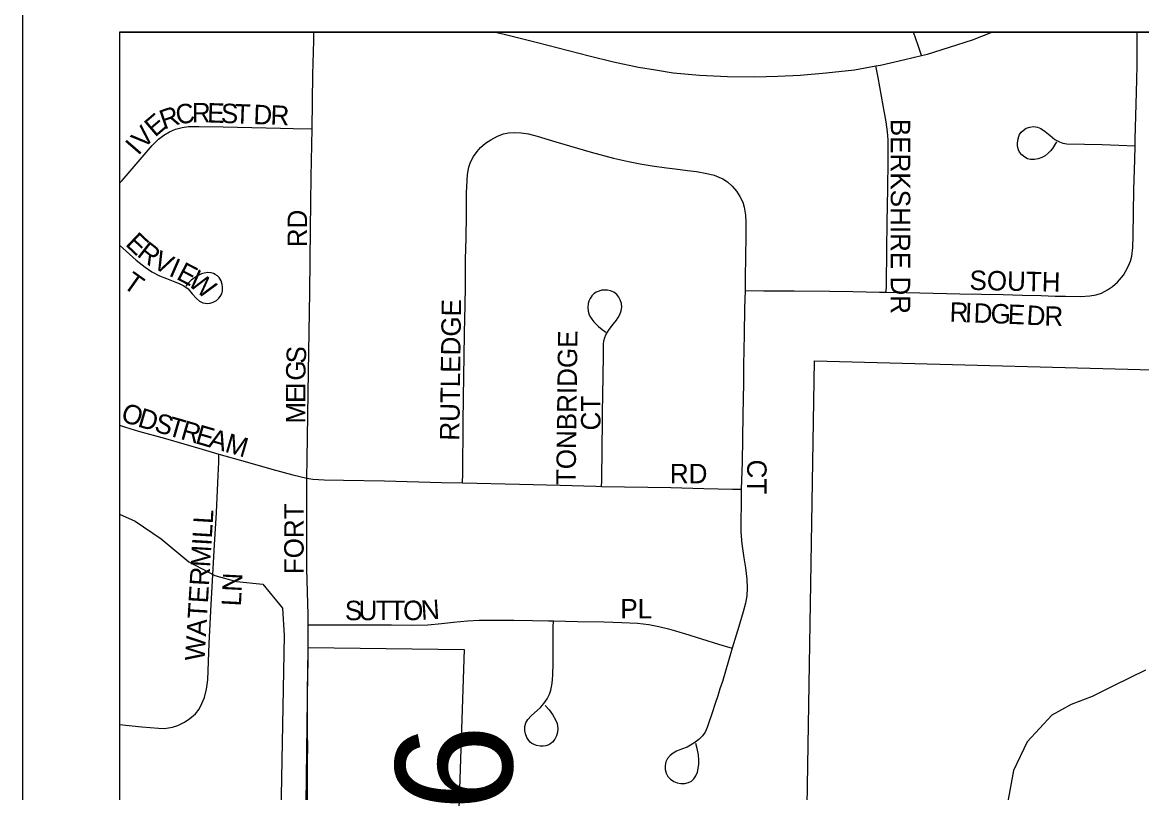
# Model space of a CAD drawing. Extents: x -5.6 to 34, y 0 to 22.
# Drawn here: x 2 to 3.152, y 20.118 to 20.91 of the extents above; entities that cross this region are included whole.
import ezdxf

# ---------------------------------------------------------------- set-up
doc = ezdxf.new("R2010")
doc.units = 0
for name, color, linetype in [('GM_X_City_Street', 7, 'Continuous'), ('GM_X_City_Street_Text', 7, 'Continuous'), ('GM_X_Corporation', 7, 'Continuous'), ('GM_X_Minor_River', 7, 'Continuous'), ('GM_X_State_Route', 7, 'Continuous'), ('GM_X_Township', 7, 'Continuous'), ('GM_X_Township_Road', 7, 'Continuous'), ('GM_X_Township_Road_Text', 7, 'Continuous'), ('SH_Data', 7, 'Continuous')]:
    doc.layers.add(name, color=color, linetype=linetype)

msp = doc.modelspace()

# ---------------------------------------------------------------- linework, layer by layer
at = {"layer": 'GM_X_City_Street'}
for points in [[(2.2982, 20.8008), (2.299, 20.8567), (2.2997, 20.8915), (2.2999, 20.9)], [(2.9252, 20.8761), (2.9215, 20.8865), (2.9168, 20.9)], [(3.1448, 20.7831), (3.1449, 20.7902), (3.1462, 20.838), (3.147, 20.8656), (3.147, 20.8814), (3.147, 20.8916), (3.147, 20.9)], [(2.8888, 20.6327), (2.8889, 20.64), (2.8895, 20.6768), (2.8897, 20.7042), (2.8903, 20.7393), (2.8908, 20.7673), (2.8908, 20.7825), (2.8908, 20.7895), (2.8902, 20.7976), (2.8886, 20.808), (2.8857, 20.8245), (2.8804, 20.8534), (2.8782, 20.8655)], [(2.1, 20.7447), (2.1025, 20.7477), (2.1334, 20.7835), (2.1402, 20.79), (2.1455, 20.7942), (2.1514, 20.7977), (2.1577, 20.8003), (2.1643, 20.802), (2.171, 20.8029), (2.1817, 20.8032), (2.2066, 20.8026), (2.2656, 20.8012), (2.2787, 20.8011), (2.2982, 20.8008)], [(2.2928, 20.4415), (2.2931, 20.4614), (2.2944, 20.5508), (2.2958, 20.6327), (2.2963, 20.6977), (2.2971, 20.7512), (2.2982, 20.8008)], [(2.4529, 20.4366), (2.453, 20.4458), (2.4535, 20.4988), (2.4538, 20.5243), (2.4544, 20.5675), (2.4548, 20.5893), (2.4552, 20.6067), (2.4554, 20.6172), (2.4558, 20.6409), (2.456, 20.6513), (2.456, 20.6665), (2.4565, 20.6881), (2.4568, 20.7127), (2.4568, 20.7301), (2.4571, 20.7357), (2.4572, 20.7408), (2.4576, 20.7478), (2.4581, 20.7537), (2.4595, 20.7614), (2.4612, 20.7664), (2.4642, 20.7722), (2.468, 20.7775), (2.4715, 20.7814), (2.4765, 20.7858), (2.4819, 20.7894), (2.4888, 20.7931), (2.495, 20.7955), (2.5001, 20.7966), (2.5067, 20.797), (2.5132, 20.7966), (2.5207, 20.7955), (2.5297, 20.793), (2.5488, 20.7873), (2.5852, 20.7767), (2.6082, 20.7706), (2.6236, 20.7671), (2.6357, 20.7647), (2.648, 20.7626), (2.6627, 20.7606), (2.6716, 20.7595), (2.6843, 20.7579), (2.6935, 20.7568), (2.7041, 20.7549), (2.7117, 20.7529), (2.7167, 20.751), (2.7207, 20.7493), (2.7254, 20.7461), (2.7304, 20.7416), (2.7347, 20.7366), (2.7383, 20.7311), (2.7411, 20.7252), (2.7425, 20.7201), (2.7439, 20.712), (2.7442, 20.7047), (2.7445, 20.6902), (2.7437, 20.6478), (2.7437, 20.6344)], [(3.0639, 20.7872), (3.0597, 20.7805), (3.0577, 20.7779), (3.0553, 20.7755), (3.0523, 20.773), (3.0488, 20.7711), (3.0451, 20.7698), (3.0413, 20.7691), (3.0373, 20.7691), (3.034, 20.7699), (3.0313, 20.7714), (3.0283, 20.7738), (3.0259, 20.7768), (3.0248, 20.7791), (3.0241, 20.7815), (3.0239, 20.7831), (3.0238, 20.7852), (3.0241, 20.789), (3.0251, 20.7928), (3.026, 20.7949), (3.0275, 20.7972), (3.0295, 20.7991), (3.0328, 20.8013), (3.0365, 20.8025), (3.0404, 20.8029), (3.0443, 20.8023), (3.0479, 20.8009), (3.0523, 20.798), (3.0573, 20.7938), (3.0624, 20.7897), (3.0669, 20.7872), (3.0706, 20.786), (3.0745, 20.7853), (3.1111, 20.7844), (3.1281, 20.7838), (3.1448, 20.7831)], [(2.8888, 20.6327), (2.9095, 20.6323), (2.9646, 20.6309), (3.0092, 20.6302), (3.0291, 20.6297), (3.0482, 20.6292), (3.0625, 20.6286), (3.0733, 20.6287), (3.0891, 20.6282), (3.0982, 20.6289), (3.1047, 20.6301), (3.1101, 20.6317), (3.1166, 20.6351), (3.1216, 20.6385), (3.1267, 20.6429), (3.1328, 20.6502), (3.135, 20.654), (3.1382, 20.6597), (3.1402, 20.6646), (3.1415, 20.6696), (3.1425, 20.6788), (3.1428, 20.6906), (3.1437, 20.7378), (3.1446, 20.7692), (3.1448, 20.7831)], [(2.1, 20.6809), (2.117, 20.6656), (2.1262, 20.6585), (2.1331, 20.6537), (2.1411, 20.6496), (2.1483, 20.6467), (2.155, 20.6441), (2.1612, 20.6418), (2.1662, 20.6392), (2.1704, 20.636), (2.1748, 20.6311), (2.1791, 20.6262), (2.1821, 20.6236), (2.1835, 20.6227), (2.1856, 20.6219), (2.1881, 20.6213), (2.1902, 20.6212), (2.1933, 20.6214), (2.1963, 20.6224), (2.1996, 20.6243), (2.202, 20.6264), (2.2035, 20.6281), (2.2051, 20.631), (2.2058, 20.634), (2.206, 20.638), (2.2056, 20.6406), (2.2045, 20.6444), (2.2024, 20.6477), (2.2006, 20.6496), (2.1984, 20.651), (2.1965, 20.6519), (2.1941, 20.6526), (2.1908, 20.6528), (2.1869, 20.6522), (2.1844, 20.6516), (2.1817, 20.6503), (2.1791, 20.6489), (2.1761, 20.6469), (2.1738, 20.6449), (2.1714, 20.6427), (2.1683, 20.6389)], [(2.596, 20.433), (2.5961, 20.4387), (2.5965, 20.4739), (2.5968, 20.4976), (2.5969, 20.5094), (2.5972, 20.5265), (2.5978, 20.5673), (2.598, 20.5791), (2.5984, 20.5826), (2.5992, 20.586), (2.6004, 20.589), (2.6036, 20.5943), (2.6081, 20.6), (2.6111, 20.6039), (2.6131, 20.6067), (2.6148, 20.6098), (2.6162, 20.6135), (2.6166, 20.6173), (2.6164, 20.6212), (2.6151, 20.6249), (2.6136, 20.6276), (2.6115, 20.6302), (2.6085, 20.6326), (2.6051, 20.6342), (2.602, 20.6349), (2.599, 20.6349), (2.596, 20.6347), (2.5933, 20.6339), (2.5905, 20.6326), (2.5881, 20.6309), (2.5859, 20.6289), (2.5842, 20.6263), (2.5828, 20.6236), (2.5821, 20.6209), (2.5816, 20.617), (2.5821, 20.6132), (2.5833, 20.6094), (2.5845, 20.6069), (2.5858, 20.6049), (2.588, 20.6021), (2.5902, 20.5999), (2.5929, 20.5974), (2.5966, 20.5943), (2.6002, 20.5916)], [(2.7437, 20.6344), (2.7431, 20.6161), (2.7425, 20.5892), (2.742, 20.5577), (2.742, 20.5393), (2.7412, 20.5066), (2.7405, 20.458), (2.7396, 20.4301)], [(2.7437, 20.6344), (2.7627, 20.6341), (2.777, 20.6341), (2.7941, 20.634), (2.8308, 20.6336), (2.8544, 20.6333), (2.882, 20.6328), (2.8888, 20.6327)], [(2.1, 20.4961), (2.1062, 20.4939), (2.1196, 20.4898), (2.1473, 20.4821), (2.1851, 20.4712), (2.2022, 20.4663)], [(2.1, 20.1883), (2.1228, 20.1857), (2.14, 20.1844), (2.1463, 20.1842), (2.1545, 20.1853), (2.16, 20.1872), (2.1667, 20.1905), (2.1723, 20.1942), (2.1782, 20.199), (2.1819, 20.2039), (2.1848, 20.2098), (2.1874, 20.2161), (2.1896, 20.2246), (2.1908, 20.2342), (2.1922, 20.2713), (2.1944, 20.3117), (2.1977, 20.3728), (2.1996, 20.4061), (2.2014, 20.4443), (2.2021, 20.458), (2.2022, 20.4663)], [(2.2022, 20.4663), (2.2291, 20.4586), (2.2567, 20.4508), (2.2783, 20.4448), (2.2928, 20.4415)], [(2.294, 20.2908), (2.294, 20.301), (2.2928, 20.3482), (2.2926, 20.3907), (2.2928, 20.4415)], [(2.2928, 20.4415), (2.2988, 20.4406), (2.3104, 20.4398), (2.3304, 20.4394), (2.3724, 20.4386), (2.4313, 20.4371), (2.4529, 20.4366)], [(2.4529, 20.4366), (2.5113, 20.4352), (2.5532, 20.4342), (2.5899, 20.4331), (2.596, 20.433)], [(2.596, 20.433), (2.6672, 20.4317), (2.7012, 20.4309), (2.7307, 20.4303), (2.7396, 20.4301)], [(2.7396, 20.4301), (2.7395, 20.4265), (2.7392, 20.3858), (2.7401, 20.374), (2.7422, 20.3597), (2.7439, 20.3494), (2.7452, 20.3377), (2.7456, 20.3285), (2.7452, 20.3206), (2.7441, 20.3128), (2.7416, 20.304), (2.7372, 20.2889), (2.7304, 20.2665)], [(2.294, 20.2908), (2.3042, 20.2908), (2.3298, 20.2908), (2.3799, 20.2905), (2.4017, 20.2903), (2.417, 20.2908), (2.4313, 20.2919), (2.4437, 20.2933), (2.458, 20.2946), (2.4698, 20.2954), (2.487, 20.2954), (2.5056, 20.2954), (2.5247, 20.2952), (2.5412, 20.2947), (2.5463, 20.2946)], [(2.294, 20.2674), (2.294, 20.2777), (2.294, 20.2908)], [(2.538, 20.2077), (2.542, 20.2031), (2.5455, 20.1985), (2.5486, 20.1931), (2.5501, 20.1891), (2.5508, 20.1842), (2.5506, 20.1803), (2.5497, 20.1765), (2.5478, 20.173), (2.5453, 20.17), (2.5438, 20.1687), (2.5416, 20.1673), (2.5385, 20.1662), (2.5359, 20.1658), (2.5327, 20.1658), (2.5291, 20.1665), (2.5265, 20.1675), (2.5243, 20.1686), (2.5226, 20.17), (2.521, 20.1716), (2.519, 20.1748), (2.5175, 20.1784), (2.517, 20.182), (2.517, 20.186), (2.518, 20.1898), (2.52, 20.1932), (2.5234, 20.1972), (2.5331, 20.2057), (2.5366, 20.2097), (2.5401, 20.2147), (2.5425, 20.2195), (2.5438, 20.2234), (2.5449, 20.2286), (2.5454, 20.2336), (2.5459, 20.24), (2.5461, 20.2504), (2.5461, 20.2599), (2.5461, 20.2708), (2.5461, 20.2814), (2.5461, 20.2883), (2.5463, 20.2946)], [(2.5463, 20.2946), (2.571, 20.2941), (2.5983, 20.2936), (2.6166, 20.2931), (2.6327, 20.2923), (2.6446, 20.291), (2.6547, 20.2891), (2.6647, 20.2865), (2.6719, 20.2845), (2.6765, 20.283), (2.6811, 20.2816), (2.7162, 20.2709), (2.7304, 20.2665)], [(2.7304, 20.2665), (2.7265, 20.2538), (2.7202, 20.2323), (2.7176, 20.2247), (2.7154, 20.2178), (2.7127, 20.2097), (2.7096, 20.2001), (2.7059, 20.1892), (2.7046, 20.1851), (2.7025, 20.1804), (2.6997, 20.1764), (2.696, 20.1727), (2.6908, 20.1688), (2.6839, 20.1649), (2.6782, 20.1627), (2.6729, 20.1607), (2.6694, 20.1588), (2.6664, 20.1563), (2.6638, 20.1533), (2.6621, 20.1498), (2.6613, 20.1459), (2.6613, 20.142), (2.6623, 20.1382), (2.6642, 20.1348), (2.6668, 20.1319), (2.6701, 20.1297), (2.6738, 20.1282), (2.6776, 20.1275), (2.6816, 20.1276), (2.6854, 20.1286), (2.6884, 20.1299), (2.6907, 20.1322), (2.693, 20.1354), (2.6945, 20.1391), (2.6954, 20.1429), (2.696, 20.1475), (2.6961, 20.1516), (2.6956, 20.157), (2.6942, 20.1635), (2.6929, 20.1685)]]:
    msp.add_lwpolyline(points, dxfattribs=at)
at = {"layer": 'GM_X_Corporation'}
for points in [[(3.2277, 20.9), (2.1, 20.9), (2.1, 18.226), (2.1688, 18.2231), (2.1708, 18.2767), (2.3867, 18.2751), (2.1, 17.7957), (2.1, 16.1715), (2.1566, 16.1698), (2.1557, 16.0644), (2.1, 16.0648), (2.1, 15.8951), (2.1803, 15.8911), (2.1794, 15.8126), (2.1472, 15.8117), (2.1446, 15.7502), (2.1, 15.7518), (2.1, 15.0823), (2.1322, 15.0813), (2.127, 14.9352), (2.1, 14.9372), (2.1, 14.8511)], [(3.1536, 18.9777), (2.7717, 18.9999), (3.0577, 19.4693), (3.04, 19.5098), (2.9528, 19.5113), (2.9527, 19.7435), (2.6819, 19.7478), (2.6801, 19.7916), (2.6052, 19.7912), (2.6079, 19.8804), (2.7143, 19.8786), (2.8037, 19.8757), (2.8151, 20.562), (3.2274, 20.5511)]]:
    msp.add_lwpolyline(points, dxfattribs=at)
msp.add_lwpolyline([(2.294, 20.2674), (2.4545, 20.2654), (2.442, 19.8863), (2.4544, 19.8859), (2.4479, 19.5945), (2.2856, 19.6003)], close=True, dxfattribs=at)
at = {"layer": 'GM_X_Minor_River'}
for points in [[(2.1, 20.4045), (2.116, 20.3974), (2.1428, 20.3792), (2.1711, 20.3554), (2.198, 20.3413), (2.2202, 20.3353), (2.2473, 20.3324), (2.2676, 20.3079), (2.2695, 20.2798)], [(2.2695, 20.2798), (2.266, 20.0963), (2.2602, 19.871), (2.257, 19.6153), (2.2485, 19.2874), (2.2423, 19.0438), (2.2144, 19.0427), (2.1857, 19.0432), (2.1665, 19.0444), (2.1529, 19.043), (2.1385, 19.0409), (2.1192, 19.0316), (2.1086, 19.0206), (2.1004, 19.0079), (2.1, 19.0071)], [(3.1556, 20.2441), (3.1226, 20.2278), (3.1008, 20.217), (3.0791, 20.2086), (3.059, 20.1977), (3.0337, 20.1702), (3.0196, 20.1407), (3.0134, 20.1072)]]:
    msp.add_lwpolyline(points, dxfattribs=at)
at = {"layer": 'GM_X_State_Route'}
msp.add_lwpolyline([(2.4866, 20.9), (2.4957, 20.8979), (2.53, 20.8894), (2.583, 20.8759), (2.6081, 20.8697), (2.6338, 20.8641), (2.6513, 20.8612), (2.6696, 20.8584), (2.6968, 20.8559), (2.7255, 20.8546), (2.7534, 20.8542), (2.7772, 20.8549), (2.8002, 20.8557), (2.827, 20.8581), (2.856, 20.8615), (2.8782, 20.8655), (2.883, 20.8663), (2.9079, 20.8718), (2.9252, 20.8761), (2.9311, 20.8776), (2.9539, 20.8845), (2.9775, 20.8923), (2.9968, 20.8996), (2.9977, 20.9)], dxfattribs=at)
at = {"layer": 'GM_X_Township'}
msp.add_lwpolyline([(3.0636, 14.1), (8.9, 14.1), (8.9, 20.9), (2.1, 20.9), (2.1, 16.9108), (2.7242, 16.8707), (3.1388, 16.8616), (3.0745, 14.7121)], close=True, dxfattribs=at)
at = {"layer": 'GM_X_Township_Road'}
for points in [[(2.2938, 20.2421), (2.2939, 20.2494), (2.2941, 20.2589), (2.294, 20.2674)], [(2.2933, 20.1042), (2.2935, 20.1245), (2.2935, 20.1383), (2.2935, 20.1512), (2.2936, 20.1648), (2.2934, 20.1789), (2.2933, 20.1866), (2.2933, 20.1968), (2.2933, 20.2132), (2.2934, 20.2255), (2.2937, 20.24), (2.2938, 20.2421)]]:
    msp.add_lwpolyline(points, dxfattribs=at)
at = {"layer": 'SH_Data'}
for p, q in [((2, 21), (2, 14)), ((2.1, 20.9), (8.9, 20.9)), ((2.1, 20.9), (2.1, 14.1))]:
    msp.add_line(p, q, dxfattribs=at)

# ---------------------------------------------------------------- texts
at = {"layer": 'GM_X_City_Street_Text'}
for s, rotation, p in [('R', 19.2029, (2.1454, 20.7997)), ('C', 10.2527, (2.1596, 20.8047)), ('R', 359.4414, (2.1742, 20.8074)), ('E', 358.0326, (2.1899, 20.8073)), ('S', 357.978, (2.204, 20.8068)), ('T', 357.9507, (2.218, 20.8063)), ('D', 357.9671, (2.2374, 20.8056)), ('R', 357.9598, (2.255, 20.805)), ('E', 40.4946, (2.1364, 20.7915)), ('BERKSHIRE DR', 270, (2.8935, 20.8109)), ('V', 47.3499, (2.125, 20.779)), ('I', 49.1759, (2.1193, 20.7725)), ('RD', 90, (2.2929, 20.6789)), ('E', 316.6293, (2.1051, 20.6814)), ('R', 322.0512, (2.1169, 20.6704)), ('V', 333.3725, (2.1329, 20.6584)), ('I', 336.4417, (2.1497, 20.65)), ('E', 332.5062, (2.1574, 20.6467)), ('T', 324.706, (2.1024, 20.6385)), ('W', 321.3848, (2.1691, 20.6407)), ('SOUTH', 358.7519, (2.9743, 20.6351)), ('RUTLEDGE', 89.2273, (2.4495, 20.4799)), ('R', 357.8385, (2.9537, 20.6025)), ('I', 357.8142, (2.9695, 20.6019)), ('D', 357.8424, (2.9784, 20.6015)), ('G', 357.836, (2.9959, 20.6009)), ('E', 357.7039, (3.0135, 20.6002)), ('D', 356.2383, (3.0327, 20.5994)), ('R', 359.0915, (3.0514, 20.5982)), ('TONBRIDGE', 89.2907, (2.5692, 20.4342)), ('S', 87.5947, (2.2915, 20.559)), ('G', 88.8197, (2.2911, 20.5415)), ('I', 89.9563, (2.2911, 20.5328)), ('E', 89.9707, (2.2911, 20.5187)), ('CT', 90, (2.5948, 20.4905)), ('O', 341.7424, (2.1003, 20.5005)), ('D', 343.6244, (2.1177, 20.4948)), ('M', 89.9636, (2.2911, 20.4976)), ('S', 343.8564, (2.1347, 20.4898)), ('T', 343.8557, (2.1482, 20.4859)), ('R', 343.8544, (2.1617, 20.482)), ('E', 343.8402, (2.1769, 20.4776)), ('A', 343.8673, (2.1905, 20.4737)), ('M', 343.852, (2.2074, 20.4688)), ('RD', 0, (2.6662, 20.4362)), ('CT', 270, (2.7457, 20.4606)), ('WATERMILL', 86.5543, (2.1873, 20.2532)), ('FORT', 90, (2.2894, 20.3427)), ('LN', 86.9884, (2.2248, 20.3094)), ('S', 0.0273, (2.3318, 20.2954)), ('U', 0.0379, (2.3459, 20.2954)), ('T', 0.0273, (2.3635, 20.2955)), ('T', 0.0273, (2.3776, 20.2955)), ('O', 0.1054, (2.3917, 20.2955)), ('N', 3.8742, (2.4107, 20.2956)), ('PL', 0, (2.6152, 20.2972))]:
    msp.add_text(s, height=0.02, rotation=rotation, dxfattribs=at).set_placement(p)
at = {"layer": 'GM_X_Township_Road_Text'}
msp.add_text('6', height=0.12, rotation=89.5688, dxfattribs=at).set_placement((2.5036, 20.0985))

doc.saveas('drawing.dxf')
